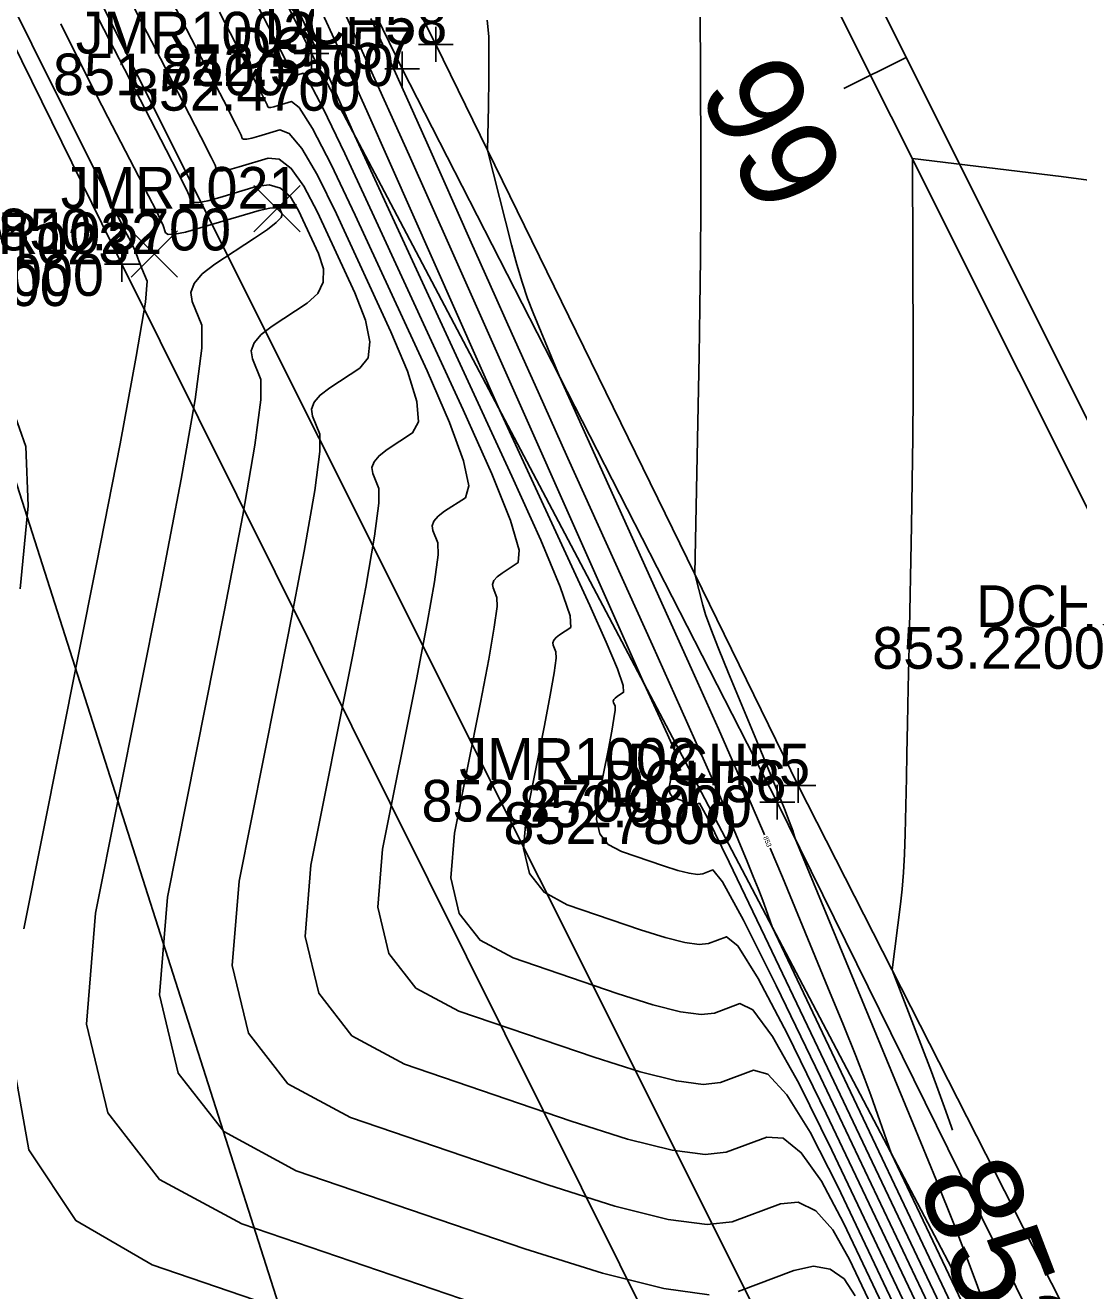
# Model space of a CAD drawing. Extents: x 1654928 to 1810050, y 486881 to 626330.
# Drawn here: x 1801379.97 to 1801410.28, y 489840.21 to 489876.6 of the extents above; entities that cross this region are included whole.
import ezdxf

# ---------------------------------------------------------------- set-up
doc = ezdxf.new("R2010")
doc.units = 0
for name, color, linetype in [('DT_X_Contour_Major', 7, 'Continuous'), ('DT_X_Contour_Minor', 7, 'Continuous'), ('PV_X_EOP', 7, 'Continuous'), ('PV_X_Shoulder', 7, 'Continuous'), ('RD_X_Fence', 7, 'Continuous'), ('RW_X_Esmt_SH', 7, 'Continuous'), ('SV_X_Break_Lines', 7, 'Continuous'), ('SV_X_Center_of_Pavt', 7, 'Continuous'), ('SV_X_CL_Survey_20', 7, 'Continuous'), ('SV_X_Occupation_Line', 7, 'Continuous'), ('SV_X_Random_Point', 7, 'Continuous'), ('SV_X_Shot_Marker', 7, 'Continuous'), ('SV_X_Text_Elevation', 7, 'Continuous'), ('SV_X_Text_Name', 7, 'Continuous')]:
    doc.layers.add(name, color=color, linetype=linetype)

msp = doc.modelspace()

# ---------------------------------------------------------------- linework, layer by layer
at = {"layer": 'DT_X_Contour_Major'}
for points in [[(1801381.806, 489879.609), (1801383.86, 489875.648), (1801384.537, 489874.342), (1801385.024, 489873.395), (1801385.323, 489872.808), (1801385.434, 489872.579), (1801385.477, 489872.448), (1801385.53, 489872.416), (1801385.656, 489872.42), (1801385.856, 489872.46), (1801386.129, 489872.535), (1801386.956, 489872.784), (1801387.277, 489872.756), (1801387.621, 489872.489), (1801387.988, 489871.98), (1801388.378, 489871.231), (1801389.448, 489868.913), (1801389.758, 489868.126), (1801389.887, 489867.503), (1801389.833, 489867.043), (1801389.598, 489866.748), (1801388.729, 489866.179), (1801388.454, 489865.968), (1801388.28, 489865.762), (1801388.207, 489865.561), (1801388.236, 489865.365), (1801388.447, 489864.849), (1801388.449, 489864.346), (1801388.299, 489863.223), (1801387.997, 489861.48), (1801387.542, 489859.117), (1801386.124, 489851.99), (1801385.925, 489849.561), (1801386.392, 489847.618), (1801387.525, 489846.162), (1801389.323, 489845.192), (1801395.006, 489843.253), (1801396.936, 489842.642), (1801398.463, 489842.261), (1801399.587, 489842.11), (1801400.308, 489842.189), (1801401.695, 489842.709), (1801402.209, 489842.755), (1801402.71, 489842.505), (1801403.2, 489841.957), (1801403.678, 489841.112), (1801404.937, 489838.464)], [(1801388.351, 489877.322), (1801389.084, 489875.712), (1801389.793, 489874.14), (1801390.478, 489872.607), (1801393.613, 489865.545), (1801396.208, 489859.922), (1801396.686, 489858.862), (1801397.008, 489858.092), (1801397.173, 489857.612), (1801397.182, 489857.421), (1801396.997, 489857.3), (1801396.939, 489857.255), (1801396.902, 489857.212), (1801396.886, 489857.169), (1801396.892, 489857.127), (1801396.937, 489857.018), (1801396.938, 489856.911), (1801396.906, 489856.672), (1801396.841, 489856.301), (1801396.745, 489855.799), (1801396.443, 489854.284), (1801396.401, 489853.767), (1801396.5, 489853.354), (1801396.741, 489853.045), (1801397.123, 489852.838), (1801398.332, 489852.426), (1801398.742, 489852.296), (1801399.066, 489852.215), (1801399.305, 489852.183), (1801399.459, 489852.2), (1801399.754, 489852.311), (1801400.03, 489851.969), (1801400.637, 489850.863), (1801401.575, 489848.991), (1801402.845, 489846.354), (1801406.672, 489838.301)], [(1801410.702, 489872.129), (1801409.766, 489872.255), (1801405.492, 489872.771), (1801405.51, 489867.192), (1801405.51, 489865.984), (1801405.503, 489864.751), (1801405.488, 489863.493), (1801405.465, 489862.21), (1801405.395, 489858.756), (1801405.371, 489857.547), (1801405.349, 489856.511), (1801405.332, 489855.648), (1801405.317, 489854.957), (1801405.283, 489853.347), (1801405.265, 489852.768), (1801405.238, 489852.238), (1801405.2, 489851.759), (1801405.152, 489851.33), (1801404.907, 489849.442), (1801406.038, 489846.501), (1801406.264, 489845.905), (1801406.455, 489845.375), (1801406.614, 489844.912), (1801406.642, 489844.823)]]:
    msp.add_lwpolyline(points, dxfattribs=at)
at = {"layer": 'DT_X_Contour_Minor'}
for points in [[(1801373.062, 489890.318), (1801380.158, 489876.06), (1801382.268, 489871.83), (1801382.614, 489871.142), (1801382.908, 489870.576), (1801383.006, 489870.385), (1801383.079, 489870.237), (1801383.129, 489870.132), (1801383.155, 489870.069), (1801383.21, 489869.907), (1801383.239, 489869.83), (1801383.278, 489869.731), (1801383.328, 489869.607), (1801383.475, 489869.248), (1801383.426, 489868.638), (1801383.166, 489867.078), (1801382.698, 489864.568), (1801382.02, 489861.108), (1801379.932, 489850.614)], [(1801384.813, 489880.719), (1801386.961, 489876.577), (1801387.5, 489875.537), (1801387.681, 489875.184), (1801387.689, 489875.159), (1801387.699, 489875.153), (1801387.723, 489875.154), (1801387.761, 489875.162), (1801387.813, 489875.176), (1801387.969, 489875.223), (1801388.141, 489874.978), (1801388.537, 489874.208), (1801389.16, 489872.913), (1801390.008, 489871.094), (1801392.571, 489865.541), (1801393.39, 489863.705), (1801393.926, 489862.362), (1801394.179, 489861.511), (1801394.148, 489861.152), (1801393.69, 489860.852), (1801393.545, 489860.74), (1801393.453, 489860.632), (1801393.415, 489860.526), (1801393.43, 489860.422), (1801393.541, 489860.15), (1801393.542, 489859.885), (1801393.463, 489859.292), (1801393.304, 489858.373), (1801393.063, 489857.126), (1801392.315, 489853.366), (1801392.211, 489852.085), (1801392.457, 489851.06), (1801393.054, 489850.292), (1801394.003, 489849.78), (1801397.001, 489848.757), (1801398.02, 489848.434), (1801398.825, 489848.233), (1801399.418, 489848.154), (1801399.799, 489848.196), (1801400.53, 489848.47), (1801400.901, 489848.284), (1801401.466, 489847.52), (1801402.225, 489846.177), (1801403.178, 489844.257), (1801405.978, 489838.367)], [(1801388.462, 489878.499), (1801389.76, 489875.65), (1801391.015, 489872.87), (1801392.225, 489870.158), (1801397.773, 489857.662), (1801398.446, 489856.204), (1801398.57, 489855.929), (1801398.653, 489855.73), (1801398.696, 489855.605), (1801398.699, 489855.556), (1801398.651, 489855.525), (1801398.635, 489855.513), (1801398.626, 489855.502), (1801398.622, 489855.49), (1801398.623, 489855.48), (1801398.635, 489855.451), (1801398.635, 489855.423), (1801398.627, 489855.362), (1801398.61, 489855.265), (1801398.585, 489855.135), (1801398.507, 489854.742), (1801398.496, 489854.609), (1801398.522, 489854.501), (1801398.584, 489854.421), (1801398.683, 489854.368), (1801398.997, 489854.261), (1801399.103, 489854.227), (1801399.187, 489854.206), (1801399.249, 489854.198), (1801399.289, 489854.202), (1801399.365, 489854.231), (1801399.594, 489853.812), (1801400.222, 489852.534), (1801401.25, 489850.398), (1801402.678, 489847.402), (1801407.019, 489838.269)], [(1801384.178, 489877.338), (1801385.046, 489875.663), (1801385.67, 489874.456), (1801386.049, 489873.717), (1801386.183, 489873.447), (1801386.214, 489873.352), (1801386.253, 489873.329), (1801386.345, 489873.332), (1801386.491, 489873.361), (1801386.69, 489873.416), (1801387.294, 489873.597), (1801387.565, 489873.497), (1801387.927, 489873.062), (1801388.379, 489872.291), (1801388.922, 489871.185), (1801390.489, 489867.789), (1801390.969, 489866.653), (1801391.233, 489865.789), (1801391.282, 489865.199), (1801391.115, 489864.883), (1801390.383, 489864.403), (1801390.151, 489864.225), (1801390.004, 489864.052), (1801389.943, 489863.883), (1801389.967, 489863.717), (1801390.145, 489863.283), (1801390.147, 489862.859), (1801390.021, 489861.912), (1801389.766, 489860.444), (1801389.382, 489858.453), (1801388.188, 489852.449), (1801388.02, 489850.402), (1801388.414, 489848.765), (1801389.368, 489847.538), (1801390.883, 489846.721), (1801395.671, 489845.088), (1801397.297, 489844.573), (1801398.584, 489844.251), (1801399.531, 489844.124), (1801400.138, 489844.191), (1801401.306, 489844.629), (1801401.773, 489844.598), (1801402.296, 489844.176), (1801402.875, 489843.364), (1801403.512, 489842.161), (1801405.284, 489838.432)], [(1801387.59, 489877.552), (1801388.064, 489876.525), (1801388.239, 489876.145), (1801388.408, 489875.773), (1801388.572, 489875.411), (1801388.73, 489875.057), (1801389.453, 489873.427), (1801393.971, 489863.639), (1801394.802, 489861.794), (1801395.362, 489860.454), (1801395.65, 489859.618), (1801395.665, 489859.287), (1801395.344, 489859.076), (1801395.242, 489858.998), (1801395.177, 489858.922), (1801395.15, 489858.847), (1801395.161, 489858.775), (1801395.239, 489858.584), (1801395.24, 489858.398), (1801395.184, 489857.982), (1801395.072, 489857.337), (1801394.904, 489856.463), (1801394.379, 489853.825), (1801394.306, 489852.926), (1801394.479, 489852.207), (1801394.898, 489851.668), (1801395.563, 489851.309), (1801397.666, 489850.592), (1801398.381, 489850.365), (1801398.946, 489850.224), (1801399.362, 489850.168), (1801399.629, 489850.198), (1801400.142, 489850.39), (1801400.465, 489850.126), (1801401.052, 489849.191), (1801401.9, 489847.584), (1801403.012, 489845.306), (1801406.325, 489838.334)], [(1801385.556, 489876.984), (1801386.774, 489874.627), (1801386.932, 489874.316), (1801386.952, 489874.255), (1801386.976, 489874.241), (1801387.034, 489874.243), (1801387.126, 489874.261), (1801387.251, 489874.296), (1801387.631, 489874.41), (1801387.853, 489874.237), (1801388.232, 489873.635), (1801388.77, 489872.602), (1801389.465, 489871.14), (1801391.53, 489866.665), (1801392.179, 489865.179), (1801392.58, 489864.076), (1801392.73, 489863.355), (1801392.632, 489863.017), (1801392.036, 489862.627), (1801391.848, 489862.483), (1801391.729, 489862.342), (1801391.679, 489862.204), (1801391.698, 489862.07), (1801391.843, 489861.716), (1801391.845, 489861.372), (1801391.742, 489860.602), (1801391.535, 489859.408), (1801391.223, 489857.79), (1801390.252, 489852.908), (1801390.115, 489851.244), (1801390.435, 489849.913), (1801391.211, 489848.915), (1801392.443, 489848.25), (1801396.336, 489846.923), (1801397.658, 489846.504), (1801398.704, 489846.242), (1801399.474, 489846.139), (1801399.969, 489846.194), (1801400.918, 489846.55), (1801401.337, 489846.441), (1801401.881, 489845.848), (1801402.55, 489844.771), (1801403.345, 489843.209), (1801405.631, 489838.399)], [(1801399.389, 489877.166), (1801399.402, 489872.958), (1801399.404, 489871.41), (1801399.397, 489869.919), (1801399.381, 489868.486), (1801399.358, 489867.111), (1801399.231, 489860.831), (1801399.461, 489859.923), (1801399.544, 489859.656), (1801399.696, 489859.242), (1801399.916, 489858.682), (1801400.204, 489857.976), (1801401.063, 489855.898), (1801401.351, 489855.199), (1801401.572, 489854.662), (1801401.725, 489854.285), (1801401.811, 489854.07), (1801401.949, 489853.71), (1801401.996, 489853.587), (1801402.032, 489853.491), (1801402.057, 489853.419), (1801402.073, 489853.374), (1801402.118, 489853.22), (1801405.511, 489845.008), (1801406.172, 489843.397), (1801406.701, 489842.082), (1801407.099, 489841.064), (1801407.365, 489840.342), (1801408.3, 489837.665)], [(1801380.991, 489876.643), (1801381.841, 489874.952), (1801382.345, 489873.964), (1801383.225, 489872.267), (1801383.517, 489871.7), (1801383.733, 489871.274), (1801383.872, 489870.988), (1801383.935, 489870.842), (1801384.002, 489870.64), (1801384.083, 489870.592), (1801384.278, 489870.598), (1801384.586, 489870.659), (1801385.007, 489870.775), (1801386.28, 489871.158), (1801386.702, 489871.276), (1801387.011, 489871.342), (1801387.207, 489871.358), (1801387.292, 489871.323), (1801387.366, 489871.161), (1801387.337, 489871.073), (1801387.194, 489870.93), (1801386.936, 489870.732), (1801386.565, 489870.479), (1801385.422, 489869.73), (1801385.06, 489869.453), (1801384.831, 489869.182), (1801384.736, 489868.918), (1801384.773, 489868.66), (1801385.051, 489867.982), (1801385.054, 489867.32), (1801384.857, 489865.843), (1801384.459, 489863.551), (1801383.86, 489860.444), (1801381.996, 489851.073), (1801381.735, 489847.879), (1801382.349, 489845.324), (1801383.838, 489843.409), (1801386.203, 489842.133), (1801393.676, 489839.584)], [(1801382.075, 489876.786), (1801384.027, 489873.021), (1801384.379, 489872.335), (1801384.598, 489871.898), (1801384.684, 489871.71), (1801384.739, 489871.544), (1801384.806, 489871.504), (1801384.967, 489871.509), (1801385.221, 489871.56), (1801385.568, 489871.655), (1801386.618, 489871.971), (1801386.989, 489872.016), (1801387.316, 489871.916), (1801387.598, 489871.669), (1801387.835, 489871.277), (1801388.407, 489870.037), (1801388.548, 489869.6), (1801388.54, 489869.216), (1801388.385, 489868.888), (1801388.082, 489868.613), (1801387.076, 489867.955), (1801386.757, 489867.71), (1801386.556, 489867.472), (1801386.471, 489867.239), (1801386.504, 489867.013), (1801386.749, 489866.415), (1801386.752, 489865.833), (1801386.578, 489864.533), (1801386.228, 489862.515), (1801385.701, 489859.781), (1801384.06, 489851.532), (1801383.83, 489848.72), (1801384.37, 489846.471), (1801385.681, 489844.785), (1801387.763, 489843.662), (1801394.341, 489841.419), (1801396.575, 489840.711), (1801398.342, 489840.27), (1801399.643, 489840.095)], [(1801389.908, 489876.801), (1801390.484, 489875.538), (1801391.022, 489874.348), (1801391.52, 489873.232), (1801392.799, 489870.353), (1801393.332, 489869.156), (1801393.974, 489867.724), (1801394.723, 489866.058), (1801395.581, 489864.157), (1801398.012, 489858.775), (1801398.834, 489856.951), (1801399.476, 489855.514), (1801399.939, 489854.464), (1801400.223, 489853.801), (1801400.739, 489852.551), (1801400.915, 489852.123), (1801401.054, 489851.777), (1801401.158, 489851.513), (1801401.225, 489851.331), (1801401.454, 489850.675), (1801408.141, 489836.605)], [(1801393.26, 489876.754), (1801393.303, 489876.278), (1801393.306, 489875.126), (1801393.304, 489874.828), (1801393.301, 489874.542), (1801393.297, 489874.267), (1801393.271, 489873.011), (1801393.962, 489870.287), (1801394.111, 489869.727), (1801394.265, 489869.215), (1801394.421, 489868.751), (1801394.582, 489868.335), (1801395.338, 489866.505), (1801399.138, 489858.092), (1801399.913, 489856.366), (1801400.606, 489854.793), (1801401.219, 489853.373), (1801401.24, 489853.322)], [(1801379.621, 489865.524), (1801379.987, 489864.495), (1801380.055, 489862.788), (1801379.825, 489860.401)], [(1801401.403, 489852.934), (1801401.751, 489852.106), (1801403.062, 489848.932), (1801403.508, 489847.845), (1801403.862, 489846.968), (1801404.125, 489846.298), (1801404.295, 489845.837), (1801404.877, 489844.17), (1801409.68, 489834.064)], [(1801379.576, 489847.059), (1801380.072, 489844.264), (1801381.422, 489842.228), (1801383.624, 489840.951), (1801390.633, 489838.561), (1801392.555, 489837.542), (1801393.062, 489836.281), (1801392.154, 489834.777), (1801389.832, 489833.029), (1801381.754, 489828.045), (1801379.039, 489826.396)], [(1801400.478, 489840.187), (1801402.083, 489840.789), (1801402.644, 489840.912), (1801403.125, 489840.833), (1801403.525, 489840.55), (1801403.845, 489840.064)]]:
    msp.add_lwpolyline(points, dxfattribs=at)
at = {"layer": 'PV_X_EOP'}
msp.add_lwpolyline([(1801513.785, 489634.043), (1801503.26, 489654.965), (1801492.692, 489675.84), (1801481.803, 489697.704), (1801472.078, 489717.629), (1801460.782, 489739.414), (1801448.005, 489764.97), (1801436.553, 489786.89), (1801425.237, 489809.697), (1801414.345, 489830.894), (1801402.21, 489854.742), (1801391.781, 489876.056), (1801380.008, 489899.32), (1801369.395, 489920.807), (1801356.62, 489946.308), (1801346.845, 489965.404), (1801335.257, 489988.444)], dxfattribs=at)
at = {"layer": 'PV_X_Shoulder'}
msp.add_lwpolyline([(1801513.053, 489633.484), (1801502.425, 489654.401), (1801492.155, 489675.438), (1801481.048, 489697.245), (1801471.095, 489717.056), (1801459.974, 489738.844), (1801446.996, 489764.517), (1801435.938, 489786.184), (1801424.33, 489809.156), (1801413.386, 489830.353), (1801401.606, 489854.259), (1801390.811, 489875.349), (1801379.301, 489898.985), (1801368.607, 489920.204), (1801355.561, 489945.921), (1801346.174, 489964.922), (1801334.144, 489988.199)], dxfattribs=at)
at = {"layer": 'RD_X_Fence'}
msp.add_lwpolyline([(1801327.157, 489980.825), (1801341.337, 489952.815), (1801353.978, 489927.719), (1801368.649, 489898.399), (1801382.749, 489869.731), (1801399.284, 489836.538), (1801405.615, 489823.327), (1801393.757, 489823.044), (1801375.98, 489823.449), (1801361.092, 489823.97), (1801335.059, 489824.221), (1801306.244, 489824.992)], dxfattribs=at)
at = {"layer": 'RW_X_Esmt_SH'}
msp.add_line((1801533.563, 489574.54), (1801308.538, 490024.454), dxfattribs=at)
at = {"layer": 'SV_X_Break_Lines'}
msp.add_lwpolyline([(1801419.479, 489816.264), (1801413.606, 489827.582), (1801399.229, 489854.903), (1801388.205, 489875.792), (1801377.391, 489897.446), (1801365.991, 489920.501), (1801353.319, 489946.375), (1801342.526, 489967.898), (1801332.595, 489987.823)], dxfattribs=at)
at = {"layer": 'SV_X_Center_of_Pavt'}
msp.add_lwpolyline([(1801523.585, 489638.313), (1801512.853, 489659.481), (1801502.374, 489680.412), (1801490.819, 489703.952), (1801481.428, 489721.68), (1801470.803, 489742.834), (1801457.335, 489769.613), (1801446.389, 489792.464), (1801435.307, 489813.792), (1801423.54, 489836.522), (1801412.234, 489859.298), (1801401.202, 489881.345), (1801390.005, 489903.67), (1801378.784, 489926.715), (1801366.669, 489950.371), (1801356.567, 489970.63), (1801345.517, 489992.708)], dxfattribs=at)
at = {"layer": 'SV_X_CL_Survey_20'}
for p, q in [((1802886.975, 486913.246), (1801128.538, 490429.055)), ((1802886.975, 486913.246), (1801128.538, 490429.055)), ((1801405.31, 489875.678), (1801403.522, 489874.783))]:
    msp.add_line(p, q, dxfattribs=at)
at = {"layer": 'SV_X_Occupation_Line'}
msp.add_lwpolyline([(1801323.637, 489975.339), (1801342.746, 489938.404), (1801356.309, 489913.548), (1801376.911, 489872.203), (1801387.619, 489838.687), (1801379.855, 489831.976), (1801347.713, 489831.536), (1801304.639, 489830.454)], dxfattribs=at)
at = {"layer": 'SV_X_Random_Point'}
for p, q in [((1801386.543, 489870.662), (1801387.877, 489871.997)), ((1801386.543, 489871.997), (1801387.877, 489870.662)), ((1801383.02, 489869.356), (1801384.354, 489870.691)), ((1801383.02, 489870.691), (1801384.354, 489869.356))]:
    msp.add_line(p, q, dxfattribs=at)
at = {"layer": 'SV_X_Shot_Marker'}
for p, q in [((1801391.781, 489876.556), (1801391.781, 489875.556)), ((1801388.205, 489876.292), (1801388.205, 489875.292)), ((1801390.811, 489875.849), (1801390.811, 489874.849)), ((1801391.281, 489876.056), (1801392.281, 489876.056)), ((1801391.781, 489876.056), (1801391.781, 489876.056)), ((1801387.705, 489875.792), (1801388.705, 489875.792)), ((1801388.205, 489875.792), (1801388.205, 489875.792)), ((1801390.311, 489875.349), (1801391.311, 489875.349)), ((1801390.811, 489875.349), (1801390.811, 489875.349)), ((1801382.749, 489870.231), (1801382.749, 489869.231)), ((1801382.249, 489869.731), (1801383.249, 489869.731)), ((1801382.749, 489869.731), (1801382.749, 489869.731)), ((1801399.229, 489855.403), (1801399.229, 489854.403)), ((1801402.21, 489855.242), (1801402.21, 489854.242)), ((1801398.729, 489854.903), (1801399.729, 489854.903)), ((1801399.229, 489854.903), (1801399.229, 489854.903)), ((1801401.606, 489854.759), (1801401.606, 489853.759)), ((1801401.71, 489854.742), (1801402.71, 489854.742)), ((1801402.21, 489854.742), (1801402.21, 489854.742)), ((1801401.106, 489854.259), (1801402.106, 489854.259)), ((1801401.606, 489854.259), (1801401.606, 489854.259))]:
    msp.add_line(p, q, dxfattribs=at)

# ---------------------------------------------------------------- texts
at = {"layer": 'DT_X_Contour_Major'}
msp.add_text('853', height=2.8, rotation=290.9204, dxfattribs=at).set_placement((1801405.602, 489843.347))
at = {"layer": 'DT_X_Contour_Minor'}
msp.add_text('853', height=0.14, rotation=292.7824, dxfattribs=at).set_placement((1801401.195, 489853.248))
at = {"layer": 'SV_X_CL_Survey_20'}
msp.add_text('66', height=2.8, rotation=116.572, dxfattribs=at).set_placement((1801403.663, 489872.265))
at = {"layer": 'SV_X_Text_Elevation'}
for s, p in [('851.7400', (1801380.77, 489874.592)), ('852.5500', (1801383.883, 489874.856)), ('852.4700', (1801382.922, 489874.149)), ('850.5700', (1801379.198, 489870.13)), ('850.5000', (1801375.543, 489868.823)), ('850.3000', (1801374.586, 489868.531)), ('853.2200', (1801404.335, 489858.098)), ('852.2700', (1801391.368, 489853.703)), ('852.9000', (1801394.179, 489853.541)), ('852.7800', (1801393.726, 489853.059))]:
    msp.add_text(s, height=1.2, dxfattribs=at).set_placement(p)
at = {"layer": 'SV_X_Text_Name'}
for s, p in [('DCH58', (1801386.85, 489876.056)), ('JMR1003', (1801381.422, 489875.792)), ('DCH57', (1801385.889, 489875.349)), ('JMR1021', (1801380.993, 489871.33)), ('JMR1022', (1801377.045, 489870.023)), ('JMR1023', (1801376.098, 489869.731)), ('DCH54', (1801407.321, 489859.298)), ('JMR1002', (1801392.456, 489854.903)), ('DCH55', (1801397.288, 489854.742)), ('DCH56', (1801396.608, 489854.259))]:
    msp.add_text(s, height=1.2, dxfattribs=at).set_placement(p)

doc.saveas('drawing.dxf')
